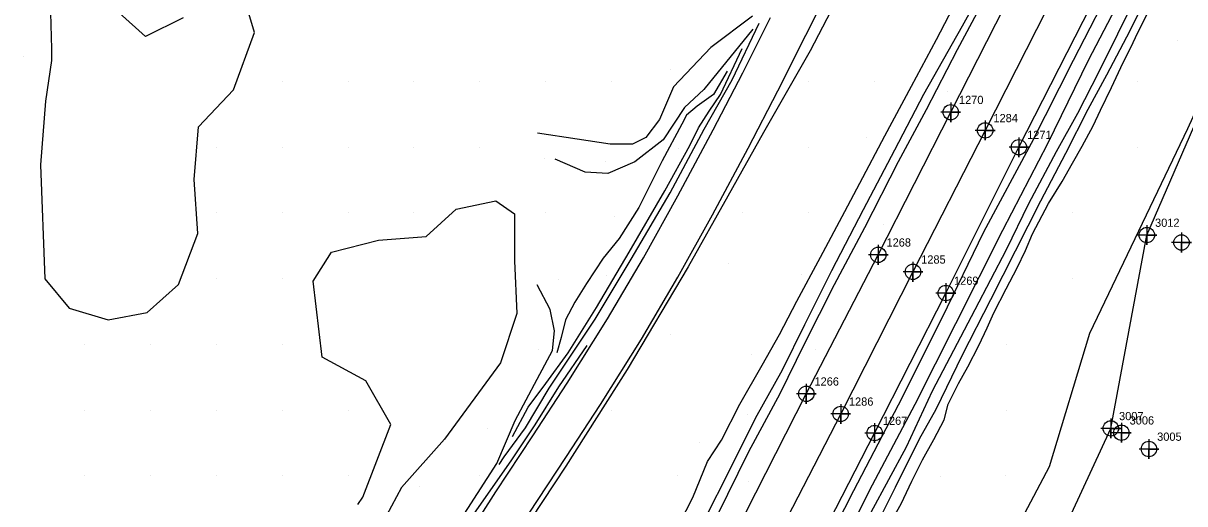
# Model space of a CAD drawing. Extents: x 2062781 to 2066835, y 358981 to 366501.
# Drawn here: x 2064838.4 to 2065191.4, y 363431.1 to 363577.2 of the extents above; entities that cross this region are included whole.
import ezdxf

# ---------------------------------------------------------------- set-up
doc = ezdxf.new("R2010")
doc.units = 0
for name, color, linetype in [('Exist DTM Breakline', 7, 'Continuous'), ('Exist DTM Breakline Cogo Number', 7, 'Continuous'), ('Exist DTM Breakline Cogo Point CELL', 7, 'Continuous'), ('Exist DTM Crownline', 7, 'Continuous'), ('Exist DTM Crownline Cogo Number', 7, 'Continuous'), ('Exist DTM Crownline Cogo Point CELL', 7, 'Continuous'), ('Exist DTM Regular Point CELL', 7, 'Continuous'), ('Exist DTM Regular Point Cogo Number', 7, 'Continuous'), ('Exist Roads EOP', 7, 'Continuous'), ('Exist Roads EOP Cogo Number', 7, 'Continuous'), ('Exist Roads EOP Cogo Point CELL', 7, 'Continuous'), ('PH Exist DTM Breakline', 7, 'Continuous'), ('PH Exist DTM Point', 7, 'Continuous')]:
    doc.layers.add(name, color=color, linetype=linetype)

msp = doc.modelspace()

# ---------------------------------------------------------------- linework, layer by layer
at = {"layer": 'Exist DTM Breakline'}
msp.add_lwpolyline([(2065004.64, 363156.66), (2065058.94, 363234.87), (2065104, 363334.19), (2065139.98, 363391.31), (2065168.9, 363454), (2065179.84, 363512.81), (2065195.44, 363548.73), (2065247.05, 363637.21), (2065277, 363695.34)], dxfattribs=at)
at = {"layer": 'Exist DTM Breakline Cogo Point CELL'}
for points in [[(2065179.84, 363515.81), (2065179.84, 363509.81), (2065179.84, 363512.81), (2065182.84, 363512.81), (2065176.84, 363512.81)], [(2065179.84, 363515.81), (2065179.84, 363509.81), (2065179.84, 363512.81), (2065182.84, 363512.81), (2065176.84, 363512.81)], [(2065179.84, 363515.81), (2065179.84, 363509.81), (2065179.84, 363512.81), (2065182.84, 363512.81), (2065176.84, 363512.81)], [(2065168.9, 363457), (2065168.9, 363451), (2065168.9, 363454), (2065171.9, 363454), (2065165.9, 363454)], [(2065168.9, 363457), (2065168.9, 363451), (2065168.9, 363454), (2065171.9, 363454), (2065165.9, 363454)], [(2065168.9, 363457), (2065168.9, 363451), (2065168.9, 363454), (2065171.9, 363454), (2065165.9, 363454)]]:
    msp.add_lwpolyline(points, dxfattribs=at)
for centre in [(2065179.84, 363512.81), (2065179.84, 363512.81), (2065179.84, 363512.81), (2065168.9, 363454), (2065168.9, 363454), (2065168.9, 363454)]:
    msp.add_circle(centre, 2.34, dxfattribs=at)
at = {"layer": 'Exist DTM Crownline'}
msp.add_lwpolyline([(2065217.01, 363714.68), (2065196.35, 363673.64), (2065174.3, 363630.59), (2065152.56, 363587.83), (2065130.72, 363544.64), (2065108.77, 363501.62), (2065086.81, 363458.41), (2065065.54, 363417.19), (2065043.91, 363374.76), (2065021.64, 363330.63), (2064998.89, 363286.49), (2064977.54, 363245.06), (2064956.39, 363203.13), (2064934.95, 363161.47)], dxfattribs=at)
at = {"layer": 'Exist DTM Crownline Cogo Point CELL'}
for points in [[(2065130.72, 363547.64), (2065130.72, 363541.64), (2065130.72, 363544.64), (2065133.72, 363544.64), (2065127.72, 363544.64)], [(2065130.72, 363547.64), (2065130.72, 363541.64), (2065130.72, 363544.64), (2065133.72, 363544.64), (2065127.72, 363544.64)], [(2065130.72, 363547.64), (2065130.72, 363541.64), (2065130.72, 363544.64), (2065133.72, 363544.64), (2065127.72, 363544.64)], [(2065108.77, 363504.62), (2065108.77, 363498.62), (2065108.77, 363501.62), (2065111.77, 363501.62), (2065105.77, 363501.62)], [(2065108.77, 363504.62), (2065108.77, 363498.62), (2065108.77, 363501.62), (2065111.77, 363501.62), (2065105.77, 363501.62)], [(2065108.77, 363504.62), (2065108.77, 363498.62), (2065108.77, 363501.62), (2065111.77, 363501.62), (2065105.77, 363501.62)], [(2065086.81, 363461.41), (2065086.81, 363455.41), (2065086.81, 363458.41), (2065089.81, 363458.41), (2065083.81, 363458.41)], [(2065086.81, 363461.41), (2065086.81, 363455.41), (2065086.81, 363458.41), (2065089.81, 363458.41), (2065083.81, 363458.41)], [(2065086.81, 363461.41), (2065086.81, 363455.41), (2065086.81, 363458.41), (2065089.81, 363458.41), (2065083.81, 363458.41)]]:
    msp.add_lwpolyline(points, dxfattribs=at)
for centre in [(2065130.72, 363544.64), (2065130.72, 363544.64), (2065130.72, 363544.64), (2065108.77, 363501.62), (2065108.77, 363501.62), (2065108.77, 363501.62), (2065086.81, 363458.41), (2065086.81, 363458.41), (2065086.81, 363458.41)]:
    msp.add_circle(centre, 2.34, dxfattribs=at)
at = {"layer": 'Exist DTM Regular Point CELL'}
for points in [[(2065190.38, 363513.54), (2065190.38, 363507.54), (2065190.38, 363510.54), (2065193.38, 363510.54), (2065187.38, 363510.54)], [(2065172.11, 363455.68), (2065172.11, 363449.68), (2065172.11, 363452.68), (2065175.11, 363452.68), (2065169.11, 363452.68)], [(2065180.48, 363450.73), (2065180.48, 363444.73), (2065180.48, 363447.73), (2065183.48, 363447.73), (2065177.48, 363447.73)]]:
    msp.add_lwpolyline(points, dxfattribs=at)
for centre in [(2065190.38, 363510.54), (2065172.11, 363452.68), (2065180.48, 363447.73)]:
    msp.add_circle(centre, 2.34, dxfattribs=at)
at = {"layer": 'Exist Roads EOP'}
for points in [[(2064924.53, 363165.86), (2064945.98, 363208.56), (2064967.54, 363250.49), (2064989.15, 363292.73), (2065011.25, 363336.17), (2065033.42, 363380.06), (2065054.8, 363422.19), (2065076.34, 363464.52), (2065098.23, 363506.8), (2065120.26, 363550.17), (2065142.18, 363593.29), (2065163.65, 363635.29), (2065185.52, 363678.33), (2065206.96, 363720.75)], [(2064946.32, 363155.04), (2064947.95, 363160.92), (2064966.7, 363197.66), (2064988.15, 363239.39), (2065009.96, 363282.16), (2065032.25, 363325.64), (2065054.28, 363368.85), (2065075.54, 363410.46), (2065097.13, 363452.58), (2065118.76, 363495.17), (2065140.96, 363539.52), (2065162.93, 363582.64), (2065184.13, 363624.16), (2065206.36, 363668.01), (2065227.4, 363709.23)]]:
    msp.add_lwpolyline(points, dxfattribs=at)
at = {"layer": 'Exist Roads EOP Cogo Point CELL'}
for points in [[(2065120.26, 363553.17), (2065120.26, 363547.17), (2065120.26, 363550.17), (2065123.26, 363550.17), (2065117.26, 363550.17)], [(2065120.26, 363553.17), (2065120.26, 363547.17), (2065120.26, 363550.17), (2065123.26, 363550.17), (2065117.26, 363550.17)], [(2065120.26, 363553.17), (2065120.26, 363547.17), (2065120.26, 363550.17), (2065123.26, 363550.17), (2065117.26, 363550.17)], [(2065140.96, 363542.52), (2065140.96, 363536.52), (2065140.96, 363539.52), (2065143.96, 363539.52), (2065137.96, 363539.52)], [(2065140.96, 363542.52), (2065140.96, 363536.52), (2065140.96, 363539.52), (2065143.96, 363539.52), (2065137.96, 363539.52)], [(2065140.96, 363542.52), (2065140.96, 363536.52), (2065140.96, 363539.52), (2065143.96, 363539.52), (2065137.96, 363539.52)], [(2065098.23, 363509.8), (2065098.23, 363503.8), (2065098.23, 363506.8), (2065101.23, 363506.8), (2065095.23, 363506.8)], [(2065098.23, 363509.8), (2065098.23, 363503.8), (2065098.23, 363506.8), (2065101.23, 363506.8), (2065095.23, 363506.8)], [(2065098.23, 363509.8), (2065098.23, 363503.8), (2065098.23, 363506.8), (2065101.23, 363506.8), (2065095.23, 363506.8)], [(2065118.76, 363498.17), (2065118.76, 363492.17), (2065118.76, 363495.17), (2065121.76, 363495.17), (2065115.76, 363495.17)], [(2065118.76, 363498.17), (2065118.76, 363492.17), (2065118.76, 363495.17), (2065121.76, 363495.17), (2065115.76, 363495.17)], [(2065118.76, 363498.17), (2065118.76, 363492.17), (2065118.76, 363495.17), (2065121.76, 363495.17), (2065115.76, 363495.17)], [(2065076.34, 363467.52), (2065076.34, 363461.52), (2065076.34, 363464.52), (2065079.34, 363464.52), (2065073.34, 363464.52)], [(2065076.34, 363467.52), (2065076.34, 363461.52), (2065076.34, 363464.52), (2065079.34, 363464.52), (2065073.34, 363464.52)], [(2065076.34, 363467.52), (2065076.34, 363461.52), (2065076.34, 363464.52), (2065079.34, 363464.52), (2065073.34, 363464.52)], [(2065097.13, 363455.58), (2065097.13, 363449.58), (2065097.13, 363452.58), (2065100.13, 363452.58), (2065094.13, 363452.58)], [(2065097.13, 363455.58), (2065097.13, 363449.58), (2065097.13, 363452.58), (2065100.13, 363452.58), (2065094.13, 363452.58)], [(2065097.13, 363455.58), (2065097.13, 363449.58), (2065097.13, 363452.58), (2065100.13, 363452.58), (2065094.13, 363452.58)]]:
    msp.add_lwpolyline(points, dxfattribs=at)
for centre in [(2065120.26, 363550.17), (2065120.26, 363550.17), (2065120.26, 363550.17), (2065140.96, 363539.52), (2065140.96, 363539.52), (2065140.96, 363539.52), (2065098.23, 363506.8), (2065098.23, 363506.8), (2065098.23, 363506.8), (2065118.76, 363495.17), (2065118.76, 363495.17), (2065118.76, 363495.17), (2065076.34, 363464.52), (2065076.34, 363464.52), (2065076.34, 363464.52), (2065097.13, 363452.58), (2065097.13, 363452.58), (2065097.13, 363452.58)]:
    msp.add_circle(centre, 2.34, dxfattribs=at)
at = {"layer": 'PH Exist DTM Breakline'}
for points in [[(2065018.95, 363181.82), (2065022.1, 363187.82), (2065046.03, 363241.26), (2065089.78, 363328.41), (2065120.97, 363386.96), (2065150.31, 363442.38), (2065162.49, 363482.96), (2065192.28, 363545.18), (2065222.26, 363610.9), (2065245.42, 363659.04), (2065275.12, 363725.13), (2065314.36, 363809.32), (2065348.05, 363874.1), (2065368.99, 363916.64)], [(2065031.84, 363394.67), (2065035.5, 363400.74), (2065041.49, 363410.98), (2065049.32, 363427.45), (2065058.87, 363446.96), (2065068.46, 363464.65), (2065075.84, 363479.71), (2065084.88, 363497.79), (2065094.14, 363515.13), (2065104.34, 363535.22), (2065112.89, 363550.97), (2065122.35, 363569.2), (2065130.51, 363584.66), (2065137.53, 363597.03), (2065142.4, 363604.96), (2065147.78, 363615.02), (2065154.26, 363627.11), (2065162.77, 363643.13), (2065171.3, 363660.12), (2065182.82, 363681.85), (2065192.16, 363700.76), (2065197.93, 363713.12), (2065203.76, 363725.75)], [(2065092.6, 363597.9), (2065077.55, 363568.88), (2065063.33, 363543.96), (2065052.48, 363524.67), (2065040.43, 363503.14), (2065021.89, 363471.92), (2065003.33, 363442.52), (2064985.53, 363415.64), (2064968.68, 363389.72), (2064952.23, 363364.84), (2064936.84, 363341.14), (2064922.47, 363316.98), (2064904.67, 363287.54), (2064892.44, 363265.29), (2064880.4, 363242.52), (2064872.46, 363228.43)], [(2065177.42, 363595.52), (2065162.04, 363565.9), (2065149.64, 363540.53), (2065136.02, 363514.2), (2065121.69, 363485.76), (2065109.37, 363461.22), (2065095.45, 363434.98), (2065082.15, 363408.32), (2065071.09, 363387.09), (2065062.32, 363369.55), (2065050.63, 363346.54), (2065038.77, 363322.15), (2065029.52, 363303.7), (2065025.69, 363297.07), (2065022.16, 363291.87), (2065019.12, 363287.75), (2065011.65, 363273.16), (2064999.35, 363247.75), (2064987.94, 363225.48), (2064978.45, 363207.76), (2064968.85, 363190.53), (2064963.06, 363180.6), (2064959.39, 363176.85)], [(2065185.89, 363596.9), (2065179.17, 363583.89), (2065173.64, 363573.03), (2065167.54, 363561.47), (2065161.95, 363551.04), (2065155.09, 363537.62), (2065147.52, 363523.11), (2065139.88, 363507.95), (2065132.37, 363493.12), (2065123.69, 363476.3), (2065115.75, 363459.76), (2065110.66, 363450.69), (2065103.4, 363435.99), (2065096.59, 363422.39), (2065088.48, 363407.21), (2065081, 363392.1), (2065075.04, 363379.99), (2065069.48, 363369), (2065065.39, 363361.43), (2065062.93, 363353.81)], [(2064873.49, 363231.78), (2064882.2, 363248.79), (2064894.08, 363271.17), (2064901.37, 363284.5), (2064909.24, 363298.26), (2064917.04, 363311.01), (2064927.73, 363328.59), (2064938.21, 363345.28), (2064950.09, 363364.12), (2064961.95, 363382.42), (2064971.49, 363397.01), (2064983.11, 363414.15), (2064992.09, 363428.18), (2065003.31, 363445.15), (2065013.84, 363461.28), (2065026.24, 363481.1), (2065037.28, 363499.97), (2065047.88, 363518.98), (2065058.7, 363539.26), (2065067.74, 363556.69), (2065076.25, 363573.62), (2065086.31, 363593.91)], [(2064998.18, 363252.86), (2065005.27, 363267.52), (2065012.72, 363282.94), (2065022.27, 363301.19), (2065034.65, 363324.79), (2065046.09, 363347.9), (2065057.99, 363371.15), (2065069.41, 363392.58), (2065079.78, 363413.36), (2065090.82, 363435.08), (2065104.34, 363461.21), (2065117.63, 363487.6), (2065130.33, 363513.76), (2065144.81, 363540.77), (2065157.54, 363565.96), (2065171.08, 363592.23)], [(2065029.89, 363395.75), (2065032.58, 363400.02), (2065035.59, 363405.39), (2065038.77, 363412.91), (2065045.41, 363426.16), (2065053.24, 363441.62), (2065060.88, 363457.15), (2065069.1, 363471.79), (2065075.91, 363485.58), (2065084.16, 363502.01), (2065093.76, 363520.58), (2065103.26, 363538.75), (2065112.06, 363555.69), (2065123.78, 363576.48), (2065130.75, 363588.96)], [(2065178.2, 363588.74), (2065170.97, 363573.94), (2065165.29, 363562.45), (2065158.78, 363549.79), (2065152.26, 363538.08), (2065143.88, 363522.34), (2065137.11, 363508.36), (2065127.58, 363490.07), (2065114.63, 363465.28), (2065106.66, 363448.27), (2065095.96, 363428.46)], [(2064890.29, 363529.75), (2064891.69, 363545.72), (2064902.24, 363557.03), (2064908.68, 363574.39), (2064905.41, 363585.41)], [(2065033.91, 363417.35), (2065041.83, 363432.93), (2065046.33, 363443.9), (2065050.57, 363450.39), (2065056.17, 363461.37), (2065062.92, 363473.22), (2065068.17, 363482.55), (2065073.46, 363492.7), (2065080.63, 363506.1), (2065088.06, 363519.96), (2065092.67, 363528.58), (2065100.26, 363543.03), (2065108.34, 363558.11), (2065115.94, 363572.3), (2065123.38, 363586.83)], [(2064886.97, 363578.84), (2064875.56, 363573.21), (2064867.55, 363580.45)], [(2065102.12, 363425.64), (2065105.14, 363431.08), (2065108.38, 363437.91), (2065111.65, 363444.39), (2065115.08, 363450.59), (2065118.24, 363456.61), (2065119.48, 363461.33), (2065122.65, 363467.69), (2065125.47, 363472.71), (2065128.83, 363479.19), (2065131.3, 363484.62), (2065133.37, 363489.1), (2065137.07, 363496.42), (2065140.39, 363502.82), (2065142.96, 363508.15), (2065145.07, 363513.2), (2065150.01, 363522.37), (2065154.16, 363529.06), (2065157.25, 363534.64), (2065160.19, 363539.84), (2065163.53, 363545.98), (2065165.77, 363550.83), (2065169.14, 363557.69), (2065172.63, 363565.31), (2065174.84, 363569.63), (2065177.24, 363574.61), (2065181.26, 363582.6)], [(2064846.72, 363580.36), (2064846.96, 363569.5), (2064847.03, 363565.9), (2064845.13, 363553.56), (2064843.62, 363534.19), (2064844.92, 363499.46), (2064852.32, 363490.59), (2064864.19, 363487.07), (2064876.06, 363489.21), (2064885.59, 363497.73), (2064891.41, 363513.33), (2064890.29, 363529.75)], [(2064862.71, 363237.07), (2064871.57, 363254.35), (2064883.52, 363276.86), (2064890.9, 363290.35), (2064898.91, 363304.37), (2064906.79, 363317.26), (2064917.52, 363334.9), (2064928.05, 363351.67), (2064939.98, 363370.58), (2064951.89, 363388.97), (2064961.51, 363403.66), (2064973.09, 363420.75), (2064982.03, 363434.73), (2064993.28, 363451.74), (2065003.73, 363467.75), (2065015.97, 363487.32), (2065026.86, 363505.92), (2065037.34, 363524.73), (2065048.08, 363544.85), (2065057.06, 363562.14), (2065065.51, 363578.98)], [(2064982.98, 363442.98), (2064984.58, 363445.3), (2064991.03, 363454.2), (2064998.23, 363466.28), (2065012.17, 363487.21), (2065023.15, 363505.49), (2065034.95, 363525.62), (2065045.31, 363544.97), (2065053.79, 363559.99), (2065062.01, 363577.24)], [(2065059.97, 363579.38), (2065047.39, 363569.87), (2065036.04, 363557.92), (2065031.72, 363547.95), (2065027.61, 363542.45), (2065023.51, 363540.5), (2065016.72, 363540.43), (2065006.7, 363541.94), (2064994.68, 363543.8)], [(2065060.16, 363575.39), (2065045.21, 363557.12), (2065039.3, 363551.64), (2065032.85, 363541.77), (2065024.29, 363535.05), (2065016.01, 363531.49), (2065009.15, 363531.93), (2065000, 363535.9)], [(2064987.12, 363451.5), (2064991.88, 363460.5), (2064997.19, 363467.69), (2065003.95, 363477), (2065012.64, 363490.74), (2065022.53, 363507.57), (2065033.35, 363526.24), (2065040.95, 363540.08), (2065043.56, 363545.42), (2065046.87, 363550.51), (2065050.3, 363555.57), (2065056.91, 363569.55)], [(2065052.35, 363562.7), (2065048.11, 363555.59), (2065043.16, 363552.06), (2065039.99, 363549.25)], [(2065039.99, 363549.25), (2065038.52, 363546.51), (2065032.53, 363535.34), (2065025.47, 363521.17), (2065019.54, 363511.8), (2065014.6, 363505.73), (2065009.55, 363498.05), (2065006.05, 363492.35), (2065003.2, 363487.04), (2065001.83, 363481.65), (2065000.52, 363476.98)], [(2064940.11, 363430.85), (2064941.62, 363433.03), (2064950.06, 363455.23), (2064942.53, 363468.42), (2064929.2, 363475.66), (2064926.52, 363498.79), (2064932.11, 363507.62), (2064946.37, 363511.24), (2064960.85, 363512.36), (2064969.94, 363520.65), (2064982.04, 363523.25), (2064987.64, 363519.29), (2064987.65, 363504.95), (2064988.44, 363488.99), (2064983.44, 363473.96), (2064966.37, 363450.74), (2064953.3, 363436.01), (2064941.15, 363413.32)], [(2064853.69, 363231.16), (2064865.72, 363253.62), (2064875.65, 363271.75), (2064886.31, 363292.48), (2064889.45, 363298.35), (2064896.68, 363309.93), (2064904.45, 363322.29), (2064917.24, 363341.37), (2064931.49, 363364.71), (2064942.77, 363382.38), (2064954.3, 363399.51), (2064967.58, 363420.47), (2064982.3, 363443.3), (2064987.85, 363456.37), (2064994.58, 363468.94), (2064999.28, 363477.71), (2064999.8, 363483.68), (2064998.49, 363490.18), (2064994.58, 363497.69)], [(2064944.79, 363381.63), (2064955.87, 363398.64), (2064966.68, 363414.29), (2064976.07, 363428.92), (2064986.92, 363444.46), (2064993.95, 363455.04), (2065001.16, 363466.62), (2065009.72, 363479.24)]]:
    msp.add_lwpolyline(points, dxfattribs=at)
at = {"layer": 'PH Exist DTM Point'}
for p, q in [((2065189.18, 363571.89), (2065189.18, 363571.89)), ((2064838.39, 363567.01), (2064838.39, 363567.01)), ((2065035.04, 363563.29), (2065035.04, 363563.29)), ((2064917.11, 363559.52), (2064917.11, 363559.52)), ((2064937.11, 363559.52), (2064937.11, 363559.52)), ((2064957.11, 363559.52), (2064957.11, 363559.52)), ((2064977.11, 363559.52), (2064977.11, 363559.52)), ((2064997.11, 363559.52), (2064997.11, 363559.52)), ((2065017.11, 363559.52), (2065017.11, 363559.52)), ((2065077.11, 363559.52), (2065077.11, 363559.52)), ((2065097.19, 363559.42), (2065097.19, 363559.42)), ((2065177.11, 363559.52), (2065177.11, 363559.52)), ((2065119.41, 363556.46), (2065119.41, 363556.46)), ((2065094.74, 363542.59), (2065094.74, 363542.59)), ((2064897.11, 363539.52), (2064897.11, 363539.52)), ((2064917.11, 363539.52), (2064917.11, 363539.52)), ((2064937.11, 363539.52), (2064937.11, 363539.52)), ((2064957.11, 363539.52), (2064957.11, 363539.52)), ((2064977.11, 363539.52), (2064977.11, 363539.52)), ((2065037.46, 363539.13), (2065037.46, 363539.13)), ((2065077.12, 363539.55), (2065077.12, 363539.55)), ((2065177.11, 363539.52), (2065177.11, 363539.52)), ((2064996.71, 363536.18), (2064996.71, 363536.18)), ((2065015.48, 363535.33), (2065015.48, 363535.33)), ((2064897.11, 363519.52), (2064897.11, 363519.52)), ((2064917.11, 363519.52), (2064917.11, 363519.52)), ((2064937.11, 363519.52), (2064937.11, 363519.52)), ((2064957.11, 363519.52), (2064957.11, 363519.52)), ((2064997.11, 363519.52), (2064997.11, 363519.52)), ((2065017.95, 363518.51), (2065017.95, 363518.51)), ((2065057.11, 363519.52), (2065057.11, 363519.52)), ((2065077.11, 363519.52), (2065077.11, 363519.52)), ((2065157.11, 363519.52), (2065157.11, 363519.52)), ((2065099.67, 363516.09), (2065099.67, 363516.09)), ((2065052.69, 363504.21), (2065052.69, 363504.21)), ((2064897.11, 363499.52), (2064897.11, 363499.52)), ((2064917.11, 363499.52), (2064917.11, 363499.52)), ((2065000.99, 363499.25), (2065000.99, 363499.25)), ((2065015.54, 363500.42), (2065015.54, 363500.42)), ((2065074.75, 363500.79), (2065074.75, 363500.79)), ((2065157.11, 363499.52), (2065157.11, 363499.52)), ((2065035.06, 363482.51), (2065035.06, 363482.51)), ((2064857.11, 363479.52), (2064857.11, 363479.52)), ((2064877.11, 363479.52), (2064877.11, 363479.52)), ((2064897.11, 363479.52), (2064897.11, 363479.52)), ((2064917.11, 363479.52), (2064917.11, 363479.52)), ((2065137.08, 363479.54), (2065137.08, 363479.54)), ((2064994.89, 363477.99), (2064994.89, 363477.99)), ((2065059.65, 363476.59), (2065059.65, 363476.59)), ((2065079.28, 363477.87), (2065079.28, 363477.87)), ((2064857.11, 363459.52), (2064857.11, 363459.52)), ((2064877.11, 363459.52), (2064877.11, 363459.52)), ((2064897.11, 363459.52), (2064897.11, 363459.52)), ((2064917.11, 363459.52), (2064917.11, 363459.52)), ((2064937.11, 363459.52), (2064937.11, 363459.52)), ((2065017.11, 363459.52), (2065017.11, 363459.52)), ((2065058.42, 363458.13), (2065058.42, 363458.13)), ((2065137.13, 363459.51), (2065137.13, 363459.51)), ((2064979.43, 363453.96), (2064979.43, 363453.96)), ((2065044, 363449.67), (2065044, 363449.67)), ((2064857.11, 363439.52), (2064857.11, 363439.52)), ((2064877.11, 363439.52), (2064877.11, 363439.52)), ((2064897.11, 363439.52), (2064897.11, 363439.52)), ((2064917.11, 363439.52), (2064917.11, 363439.52)), ((2064937.11, 363439.52), (2064937.11, 363439.52)), ((2064977.11, 363439.52), (2064977.11, 363439.52)), ((2065037.22, 363439.52), (2065037.22, 363439.52)), ((2065117.04, 363439.5), (2065117.04, 363439.5)), ((2065136.95, 363439.55), (2065136.95, 363439.55)), ((2064958.71, 363436.44), (2064958.71, 363436.44)), ((2065058.81, 363437.84), (2065058.81, 363437.84))]:
    msp.add_line(p, q, dxfattribs=at)

# ---------------------------------------------------------------- texts
at = {"layer": 'Exist DTM Breakline Cogo Number'}
for s, p in [('3012', (2065182.34, 363515.31)), ('3012', (2065182.34, 363515.31)), ('3012', (2065182.34, 363515.31)), ('3007', (2065171.4, 363456.5)), ('3007', (2065171.4, 363456.5)), ('3007', (2065171.4, 363456.5))]:
    msp.add_text(s, height=2.5, dxfattribs=at).set_placement(p)
at = {"layer": 'Exist DTM Crownline Cogo Number'}
for s, p in [('1284', (2065133.22, 363547.14)), ('1284', (2065133.22, 363547.14)), ('1284', (2065133.22, 363547.14)), ('1285', (2065111.27, 363504.12)), ('1285', (2065111.27, 363504.12)), ('1285', (2065111.27, 363504.12)), ('1286', (2065089.31, 363460.91)), ('1286', (2065089.31, 363460.91)), ('1286', (2065089.31, 363460.91))]:
    msp.add_text(s, height=2.5, dxfattribs=at).set_placement(p)
at = {"layer": 'Exist DTM Regular Point Cogo Number'}
for s, p in [('3006', (2065174.61, 363455.18)), ('3006', (2065174.61, 363455.18)), ('3006', (2065174.61, 363455.18)), ('3005', (2065182.98, 363450.23)), ('3005', (2065182.98, 363450.23)), ('3005', (2065182.98, 363450.23))]:
    msp.add_text(s, height=2.5, dxfattribs=at).set_placement(p)
at = {"layer": 'Exist Roads EOP Cogo Number'}
for s, p in [('1270', (2065122.76, 363552.67)), ('1270', (2065122.76, 363552.67)), ('1270', (2065122.76, 363552.67)), ('1271', (2065143.46, 363542.03)), ('1271', (2065143.46, 363542.03)), ('1271', (2065143.46, 363542.03)), ('1268', (2065100.73, 363509.3)), ('1268', (2065100.73, 363509.3)), ('1268', (2065100.73, 363509.3)), ('1269', (2065121.26, 363497.67)), ('1269', (2065121.26, 363497.67)), ('1269', (2065121.26, 363497.67)), ('1266', (2065078.84, 363467.02)), ('1266', (2065078.84, 363467.02)), ('1266', (2065078.84, 363467.02)), ('1267', (2065099.63, 363455.08)), ('1267', (2065099.63, 363455.08)), ('1267', (2065099.63, 363455.08))]:
    msp.add_text(s, height=2.5, dxfattribs=at).set_placement(p)

doc.saveas('drawing.dxf')
